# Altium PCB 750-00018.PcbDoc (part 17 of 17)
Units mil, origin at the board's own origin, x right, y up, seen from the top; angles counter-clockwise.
Board outline 7086.64 x 6299.21 mil, 8 copper layers (Top Layer, L2, L3, L4, L5, L6, L7, Bottom Layer), stack 60.6 mil thick; 1356 components, 1054 nets, 4851 pads, 4296 vias.
Unrouted connection lines stored in the file: 12.
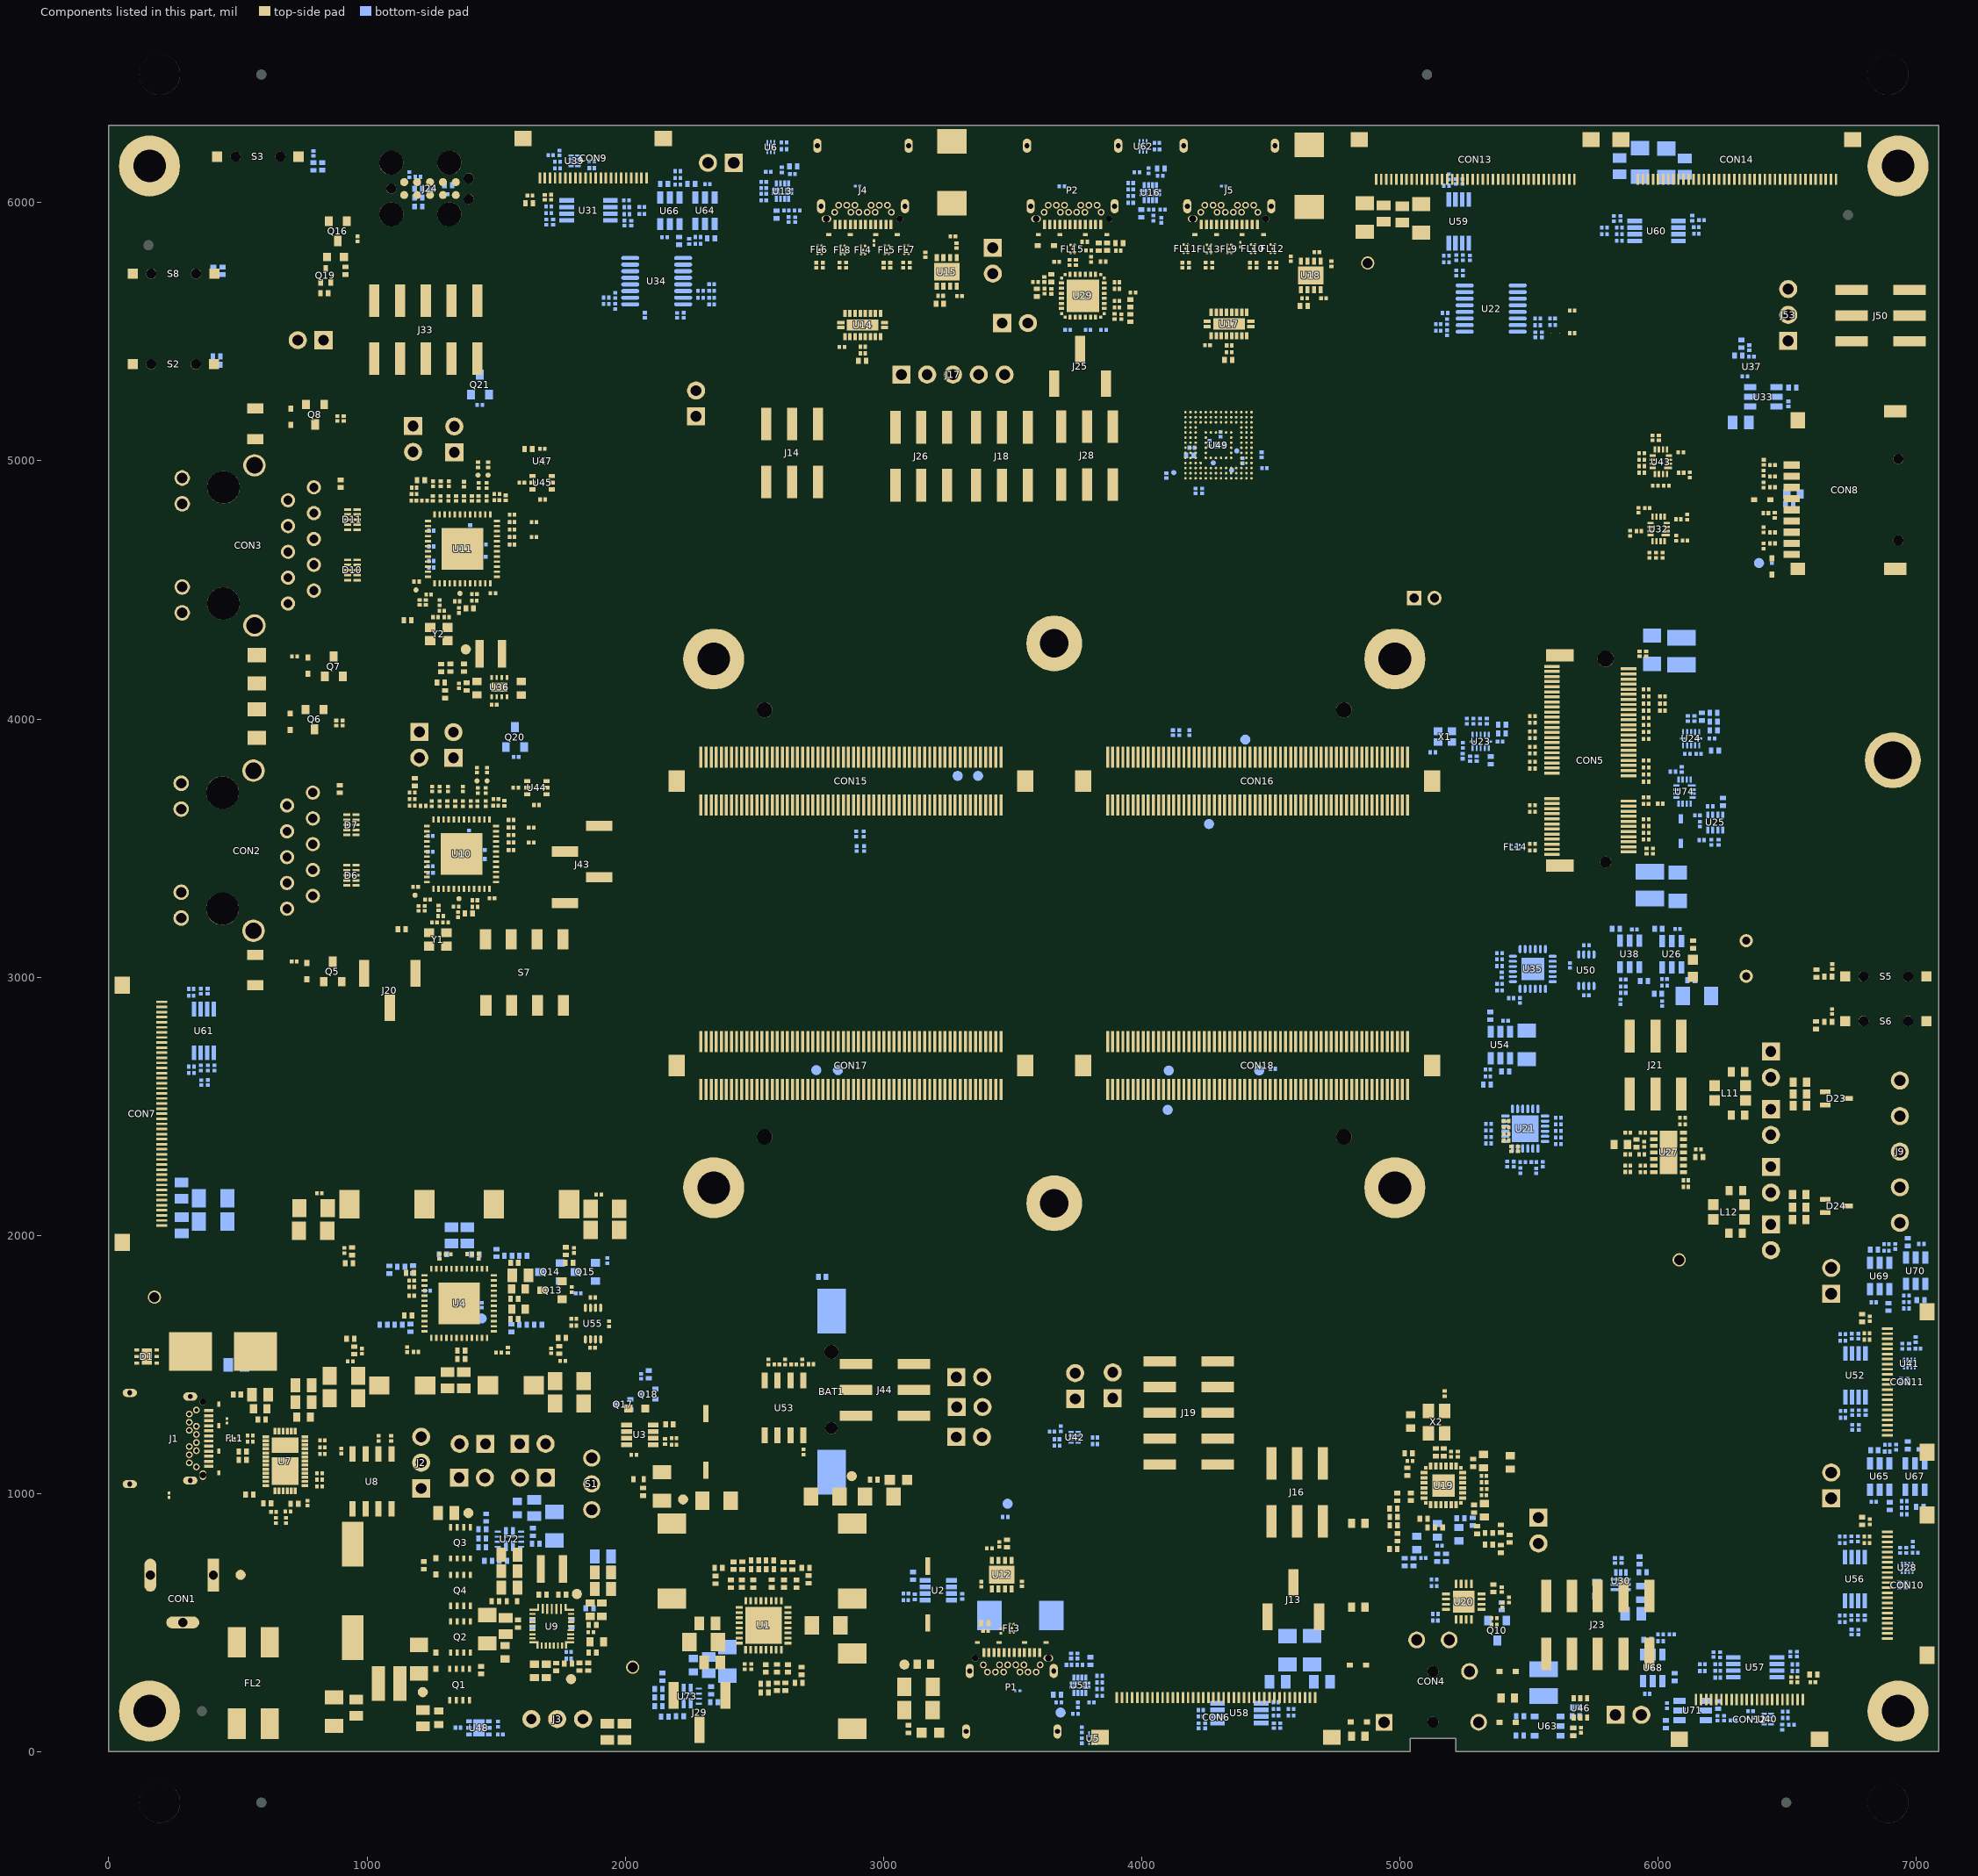
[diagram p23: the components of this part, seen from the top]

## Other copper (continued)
Bottom Layer:
  rectangle net NetU7_15: 630.69,1157.17 735.02,1217.4
  pour cut-out: 6735.52,5981.81 ccw(c6735.52,5952.12) 6705.84,5952.12 ccw(c6735.52,5952.12) 6735.52,5922.44 ccw(c6735.52,5952.12) 6765.21,5952.12 ccw(c6735.52,5952.12)
  pour cut-out: 153.48,5865.01 ccw(c153.48,5835.32) 123.79,5835.32 ccw(c153.48,5835.32) 153.48,5805.64 ccw(c153.48,5835.32) 183.16,5835.32 ccw(c153.48,5835.32)
  pour cut-out: 360.48,187.17 ccw(c360.48,157.48) 330.79,157.48 ccw(c360.48,157.48) 360.48,127.8 ccw(c360.48,157.48) 390.16,157.48 ccw(c360.48,157.48)
  region net CSI_HV: 1556.98,776.15 1572.73,776.15 1572.73,870.64 1586.68,884.6 1673.62,884.6 1690.32,901.29 1761.18,901.29 1761.18,956.41 1766.59,961.81 1766.59,976.53 1760.66,982.46 1695.93,982.46 1690.32,976.85 1690.32,956.41 1665.52,931.61 1564.12,931.61 1556.98,924.47
  pour cut-out: 7020.34,1093.61 7020.34,1089.61 7006.35,1089.61 7006.35,1093.61
  region net VDD_3V3: 6161.12,185.89 6482.03,185.89 6495.05,172.88 6495.05,122.93 6514.39,122.93 6519.03,118.29 6519.03,96.64 6532.87,96.64 6550.98,114.75 6550.98,283.07 6571.45,303.54 6571.45,365.04 6561.4,375.09 6494.09,375.09 6483.1,386.08 6260.9,386.08 6247.89,373.07 6247.59,373.37 6156.38,373.37 6140.75,357.74 6140.75,287.32 6158.45,269.61 6218.44,269.61 6228.24,279.42 6228.24,295.24 6178.4,295.24 6168.73,304.91 6168.73,346.6 6178.5,356.37 6504.75,356.37 6504.75,356.3 6522.83,356.3 6532.94,346.2 6532.94,301.81 6524.95,293.82 6524.95,230.82 6512.01,217.87 6169.47,217.87 6161.12,209.52
  region net VDD_3V3: 6923.73,1612.26 6938.16,1597.84 6938.16,1573.72 6979.75,1573.72 6979.75,1594.12 6984.55,1598.92 7005.3,1598.92 7005.3,1632.47 7046.4,1673.57 7046.4,1835.11 7022.78,1835.11 7022.78,1691.94 6962.36,1631.52 6777.84,1631.52 6758.59,1650.77 6723.15,1650.77 6718.03,1645.65 6718.03,1584.08 6732.47,1584.08 6732.47,1603.89 6740.85,1612.27 6767.43,1612.27
  region net VDD_3V3: 6716.5,800.01 6730.36,800.01 6730.36,818.09 6740.46,828.2 6784.64,828.2 6799.75,813.09 6920,813.09 6928.6,804.48 6928.6,783.06 6969.16,783.06 6969.32,783.22 6969.32,803.42 6972.86,806.96 6994.57,806.96 7043.96,856.34 7043.96,1038.49 7020.34,1038.49 7020.34,868.47 6995.31,843.44 6803.16,843.44 6779.9,866.71 6721.62,866.71 6716.5,861.59
  pour cut-out: 2160.66,5944.53 2160.66,5940.53 2146.67,5940.53 2146.67,5944.53
  pour cut-out: 2320.52,5992.41 2320.52,5996.41 2334.5,5996.41 2334.5,5992.41
  pour cut-out: 6110,172.11 6106,172.11 6106,186.1 6110,186.1
  pour cut-out: 5967.91,301.59 5967.91,297.59 5953.92,297.59 5953.92,301.59
  pour cut-out: 6845.44,1042.32 6845.44,1038.32 6831.46,1038.32 6831.46,1042.32
  pour cut-out: 6845.44,1818.75 6845.44,1814.75 6831.46,1814.75 6831.46,1818.75
  pour cut-out: 7008.79,1886.51 7008.79,1890.51 7022.77,1890.51 7022.77,1886.51
  region net VDD_3V3_B: 7022.41,1890.23 7022.41,1990.03 7022.41,2002.81 7026.38,2006.78 7046.4,2006.78 7046.4,1890.23
  region net VDD_3V3_C: 7020.34,1093.61 7043.96,1093.61 7043.96,1140.85 7048.51,1145.4 7048.51,1218.43 7040.98,1225.96 7025.52,1225.96 7020.34,1220.77
  region net VDD_3V3_D: 6106,209.52 6015.65,209.52 6001.01,194.88 6001.01,184.15 6008.25,176.91 6016.98,176.91 6021.17,181.1 6053.96,181.1 6058.75,185.89 6106,185.89
  region net VDD_3V3: 2123.26,5995.65 2123.26,6043.48 2102.79,6063.95 2102.79,6083.99 2111.59,6092.8 2135.91,6092.8 2144.37,6084.34 2144.37,6053.3 2146.88,6050.79 2146.88,5995.65
  region net VDD_3V3_A: 2146.88,5940.53 2146.88,5876.27 2149.62,5873.52 2149.62,5857.7 2142.36,5850.43 2112.85,5850.43 2105.21,5858.07 2105.21,5875.24 2123.26,5893.29 2123.26,5940.53
  region net DP_HV: 2344.88,267.76 2420.98,191.66 2439.91,191.66 2450.46,202.21 2450.46,302.78 2430.33,322.9 2246.03,322.9 2246.03,285.38 2246.03,168.19 2261.78,168.19 2261.78,252.01 2277.53,267.76
  region net LS_12V: 1460.55,144.97 1460.55,110.1 1536.1,110.1 1544.75,118.74 1544.75,147.94 1532.72,159.96 1475.55,159.96
  region net VPD_output: 1424.84,912.66 1487.4,912.66 1529.42,870.64 1529.42,829.3 1545.17,829.3 1545.17,953.05 1527.43,970.79 1351.17,970.79 1315.84,935.46 1315.84,815.65 1336.22,795.26 1387.55,795.26 1407.61,815.32 1407.61,895.43
  region net V_SYS: 1299.98,1986.92 1299.98,1905.57 1315.1,1890.46 1397.86,1890.46 1414.13,1906.73 1414.13,1986.92
  region net DP_HV: 4694.89,366.07 4694.89,310.96 4684.04,300.1 4684.04,244.6 4633.34,244.6 4624.03,253.91 4624.03,366.07
  region net DP_HV: 241.46,2088.86 256.88,2088.86 375.99,2088.86 375.99,2018 320.87,2018 320.87,2037.97 307.33,2051.5 236.57,2051.5 233.66,2054.42 233.66,2081.06
  region net PER_12V: 1405.43,110.1 1365.12,110.1 1339.25,135.98 1339.25,145.5 1345.17,151.42 1398.86,151.42 1405.43,144.86
  region net VDD_CSI_5V: 6638.09,1132.68 6716.88,1132.68 6756.12,1093.44 6831.66,1093.44 6831.66,1179.03 6796.33,1214.36 6518.49,1214.36 6010.87,706.74 5946.12,706.74 5946.12,683.06 5963.9,683.06 5985.95,661.01 5985.95,616.11 5978.04,608.2 5921.13,608.2 5894.8,634.54 5865.27,634.54 5865.27,593.92 5887.37,571.82 5905.77,571.82 5916.3,561.29 5916.3,508.14 5873.06,464.9 5873.06,367.99 5888.34,352.71 5954.13,352.71 5954.13,448.71
  region net VDD_CSI_5V: 2334.3,5941.3 2334.3,5877.79 2337.86,5874.23 2337.86,5850.54 2370.66,5850.54 2388.88,5868.76 2388.88,5910.34 2357.92,5941.3
  region net VDD_CSI_5V_A: 2334.3,5996.41 2334.3,6050.66 2321.13,6063.83 2321.13,6087.2 2285.33,6123 2285.33,6154.06 2355.33,6154.06 2355.33,6113.36 2381.28,6087.41 2381.28,6019.78 2357.92,5996.41
  region net VDD_CSI_5V: 6831.66,1869.87 6831.66,1955.46 6824.42,1962.7 6786.34,1962.7 6777.6,1953.96 6777.6,1900.3 6808.04,1869.87
  region net VDD_CSI_5V_B: 6831.66,1814.75 6779.31,1814.75 6685.08,1908.98 6670.39,1908.98 6670.39,1838.98 6689.76,1838.98 6795.78,1732.96 6831.66,1732.96
  region net VDD_CSI_5V_C: 6831.66,1038.32 6782.26,1038.32 6704.02,1116.56 6670.39,1116.56 6670.39,1046.56 6698.49,1046.56 6785.62,959.42 6831.66,959.42
  region net VDD_CSI_5V_D: 5930.5,297.59 5900.02,267.1 5900.02,143.18 5954.13,143.18 5954.13,195.3 5954.13,297.59
  region net NetL14_1: 5865.27,654.22 5977.81,654.22 5977.81,619.96 5972.84,614.99 5928.47,614.99 5901.04,642.41 5865.27,642.41
  region net VDD_5V: 5501.06,245.9 5501.06,185.44 5568.41,185.44 5606.3,147.56 5606.3,127.05 5607.44,125.91 5675.7,125.91 5675.7,205.46 5635.25,245.9
  region net VDD_3V3: 6003.62,6039.32 5996.27,6046.67 5996.27,6126.46 6129.85,6126.46 6129.85,6081.8 6087.37,6039.32
  region net VDD_3V3: 6078.61,3061.76 6078.61,3014.52 6067.85,3003.76 6067.85,2892.07 6122.97,2892.07 6122.97,3041.03 6102.23,3061.76
  region net VDD_3V3: 5414.29,2627.17 5417.69,2623.78 5520.26,2623.78 5555.61,2659.13 5555.61,2700.19 5545.52,2710.28 5414.52,2710.28 5414.29,2710.06
  region net VDD_3V3: 1801.82,5941.26 1801.82,5922.46 1744.82,5922.46 1739.87,5927.41 1664.45,5927.41 1654.23,5937.62 1654.23,5975.9 1670.59,5992.25 1700.59,5992.25 1700.59,5951.14 1700.38,5950.93 1710.05,5941.26 1712.64,5941.26
  region net VDD_3V3: 4528.7,365.4 4528.7,310.29 4539.55,299.43 4539.55,243.93 4592.09,243.93 4599.56,251.4 4599.56,365.4
  region net VDD_3V3: 308.26,2160.81 321.13,2173.68 321.13,2179.11 376.25,2179.11 376.25,2108.25 236.97,2108.25 232.09,2113.13 232.09,2158.48 234.42,2160.81
  region net NetC262_1: 6339.21,5381.49 6339.21,5370.24 6349.44,5370.24 6355.74,5376.54 6355.75,5393.09 6358.26,5395.61 6358.26,5411.44 6360.99,5414.16 6360.99,5434.91 6345.18,5434.91 6334.2,5445.89 6334.2,5447.53 6316.68,5447.53 6316.68,5396.17 6324.52,5396.17
  region net NetC262_1: 6339.21,5370.24 6339.21,5378.9
  region net NetC256_2: 6994.63,802.23 6978.81,802.23 6978.81,749.8 6967.65,738.64 6967.65,731.18 6989.3,731.18 6989.3,736.51 6992.38,739.59 6992.38,779.02 6994.63,781.28
  region net NetC260_2: 3716.66,1220.58 3722.25,1220.58 3722.25,1242.09 3716.38,1247.96 3655.44,1247.96 3655.44,1232.14 3705.11,1232.14
  region net NetC257_2: 1714.23,6191.7 1714.23,6175.88 1764.86,6175.88 1776.02,6164.72 1785.37,6164.72 1785.37,6186.37 1779.95,6186.37 1776.87,6189.45 1737.43,6189.45 1735.18,6191.7
  region net NetC259_2: 7003.2,1592.99 6987.38,1592.99 6987.38,1540.87 6976.22,1529.71 6976.22,1522.11 6997.87,1522.11 6997.87,1527.28 7000.95,1530.36 7000.95,1569.79 7003.2,1572.05
  region net NetC258_2: 6513.18,96.64 6513.18,112.47 6462.55,112.47 6451.4,123.63 6442.81,123.63 6442.81,101.97 6447.47,101.97 6450.55,98.9 6489.98,98.9 6492.24,96.64
  region net VDD_SD_3V3: 6332.51,5221.61 6333.11,5221.01 6333.11,5115.92 6338.48,5110.56 6390.95,5110.56 6398.35,5117.96 6398.35,5179.39 6379.75,5197.98 6379.75,5221.61
  region net NetC297_1: 6502.14,4819.35 6502.14,4843.06 6512.55,4853.48 6512.55,4889.03 6512.38,4889.2 6484.38,4889.2 6454.96,4859.79 6454.96,4828.04 6463.65,4819.35
  region net CSI_HV: 5827.11,673.91 5799.68,701.33 5742.36,701.33 5737.74,696.71 5737.74,648.58 5744.49,641.83 5780.49,641.83 5800.76,662.1 5846.24,662.1 5846.24,673.91
  region net VDD_3V3_M2: 6078.02,3194.25 6078.02,3116.88 6359.54,3116.88 6454.7,3212.04 6454.7,4074.77 6288.91,4240.57 6144.98,4240.57 6144.98,4240.38 5911.11,4240.38 5911.11,4239.99 5902.27,4231.16 5902.27,4181.2 5945.49,4137.99 6247.57,4137.99 6359.54,4026.01 6359.54,3539.86 6305.96,3486.27 5937.7,3486.27 5912.19,3460.76 5912.19,3378.43 6213.71,3378.43 6230.22,3361.91 6230.22,3225.15 6205.11,3200.03 6083.81,3200.03
  region net NetC233_1: 6157.32,4003.01 6155.37,4001.06 6155.37,3938.05 6163.24,3938.05 6169.6,3944.4 6208.88,3944.4 6208.88,4035.49 6208.64,4035.72 6190.86,4035.72 6190.86,4012.04 6181.84,4003.01
  region net USB_A_VBUS: 3362.9,488.34 3362.9,462.49 3394.05,431.34 3426.92,431.34 3457.39,461.81 3457.39,488.34
  region net U28_SW2: 1766.15,528.26 1734.1,528.26 1729.07,523.23 1729.07,492 1735.73,485.34 1767.89,485.34 1772.12,489.57 1772.12,522.3
  region net U28_SW1: 1665.75,529.02 1659.03,522.3 1659.03,491.55 1664.82,485.76 1694.91,485.76 1701.79,492.65 1701.71,492.73 1701.71,522.87 1695.57,529.02
  region net NetC76_2: 506.78,1426.66 516.08,1417.36 581.83,1417.36 588.74,1424.27 588.74,1509.37 574.02,1524.1 506.78,1524.1
  region net VDD_2V5: 2189.09,5606.29 2189.09,5570.47 2193.12,5566.44 2234.61,5566.44 2259.09,5590.92 2259.09,5606.29
  region net VDD_2V5: 5456.05,5495.86 5482.06,5469.84 5494.92,5469.84 5516.23,5491.15 5558.01,5491.15 5558.01,5505 5555.22,5507.78 5456.05,5507.78
  region net VDD_2V5: 841.07,2173.2 837.28,2169.41 837.28,2148.99 840.32,2145.95 880.54,2145.95 883.54,2148.96 883.54,2169.01 879.36,2173.2
  region net VDD_1V8: 5593.81,5559.43 5594.03,5559.2 5594.03,5517.54 5627.53,5517.54 5631.01,5521.02 5631.01,5555.73 5627.31,5559.43
  region net VDD_1V8: 5390.9,3920.92 5390.9,3902.75 5387.32,3899.17 5340.49,3899.17 5340.49,3845.9 5362.78,3845.9 5404.74,3887.87 5404.74,3920.92
  region net VDD_5V: 4037.87,5936.77 4037.87,5852.45 4068.76,5821.56 4090.86,5821.56 4097.84,5828.54 4097.84,5898.21 4087.77,5908.28 4087.77,5926.06 4064.08,5926.06 4053.69,5936.45 4053.69,5936.77
  region net VDD_5V: 5915.41,3062.2 5915.41,2980.19 5921.6,2974 5939.38,2974 5939.38,3061.86 5939.04,3062.2
  region net VDD_5V: 4052.74,6067.99 4052.74,6140.88 4050.57,6143.05 4068.34,6143.05 4068.34,6083.48 4063.2,6078.34 4063.2,6067.99
  region net VDD_5V: 2627.17,6066.14 2627.17,6152.27 2643.62,6152.27 2643.62,6090.48 2638.48,6085.33 2638.48,6066.14
  region net VDD_5V: 2625.09,5931.22 2625.09,5836.11 2633.45,5827.74 2660.58,5827.74 2668.93,5836.09 2668.93,5925.38 2663.09,5931.22
  region net VDD_5V: 3678.59,208.89 3682.09,205.4 3682.09,183.22 3709.42,183.22 3740.75,214.54 3740.75,226.1 3740.75,237.88 3683.89,237.88 3678.59,232.58
  pour cut-out: 1737.28,4558.7 1737.28,4550.11 1741.22,4550.11 1741.22,4558.7
  pour cut-out: 5583.56,3547.03 5583.56,4597.25 5583.56,4736.88 5729.14,4882.46 5729.14,4969.9 5827.13,5067.89 6067.74,5065.61 6144.74,4988.61 6144.74,4540.78 6011.58,4407.62 5964.27,4407.62 5878.71,4322.06 5878.71,4096.25 5813.49,4031.04 5814.14,4030.39 5814.14,3631.99 5739.84,3557.7 5699.07,3557.7 5671.74,3585.02 5658.99,3585.02 5621.34,3547.37 5584.29,3547.37
  pour cut-out: 4029.85,3890.17 4006.77,3867.09 3926.5,3867.09 3883.85,3909.73 3883.85,4085.84 3946.07,4148.05 4024.33,4148.05 4112.13,4060.25 4112.13,4016.1
  pour cut-out: 6351.17,4943.27 6346.44,4938.54 6333.79,4951.18 6338.46,4955.85 6350.94,4943.37
  pour cut-out: 4714.42,4468.12 4719.15,4472.85 4731.8,4460.2 4727.13,4455.53 4714.65,4468.01
  pour cut-out: 1597.4,3642.16 1604.09,3642.16 1604.09,3624.28 1597.49,3624.28 1597.49,3641.92
  pour cut-out: 1596.65,3355.1 1603.34,3355.1 1603.34,3337.22 1596.74,3337.22 1596.74,3354.86
  pour cut-out: 1612.88,3389.54 1619.57,3389.54 1619.57,3371.66 1612.97,3371.66 1612.97,3389.31
  pour cut-out: 1625.89,3499.46 1632.58,3499.46 1632.58,3481.58 1625.98,3481.58 1625.98,3499.23
  pour cut-out: 1629.74,3567.37 1636.43,3567.37 1636.43,3549.48 1629.83,3549.48 1629.83,3567.13
  text ".layer_Name" at 11119.18,-642.91 h100

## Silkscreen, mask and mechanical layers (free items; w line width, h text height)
Top Overlay:
  drawing of 230 lines, arcs and shapes, not listed
  text "Debug UART reset" at 3385.36,6054.63 h35
  text "Wake-up" at 399.02,6000.84 h65
  text "CSI_A" at 1868.69,5895.85 h100
  text "LVDS_D" at 5170.98,5867.49 h100
  text "LVDS_E" at 6088.95,5867.49 h100
  text "Debug UART" at 4100.61,5827.14 h80 r90
  text "RTS" at 6701.78,5825.85 h30
  text "RX" at 6859.87,5825.42 h30
  text "CTS" at 6701.78,5776.1 h30
  text "TX" at 6859.87,5775.66 h30
  text "MCU_UART_B" at 6182.63,5738.38 h35
  text "GND" at 6700.99,5724.88 h30
  text "OSM_1V8" at 6859.87,5721.11 h30
  text "RESET" at 1728.68,5708.49 h35 r90
  text "nTRST" at 1816.69,5707.29 h35 r90
  text "TDI" at 1907.55,5707.29 h35 r90
  text "NC" at 1987.19,5707.29 h35 r90
  text "TDO" at 2074.88,5703.34 h35 r90
  text "GND" at 2427.38,5618.62 h30 r90
  text "CTS_GPIO_B_3" at 2503.94,5618.62 h25 r90
  text "RTS_GPIO_B_2" at 2580.5,5618.62 h25 r90
  text "USB_C" at 2757.51,5606.08 h100
  text "GPIO_A_4" at 3555.87,5603.25 h35 r90
  text "USB_D" at 4223.03,5597.32 h100
  text "GND" at 4809.57,5596.41 h100
  text "2-3 : J50 CON" at 6157.61,5594.76 h25
  text "TMS" at 1817.11,5582.63 h35 r90
  text "GND" at 1907.97,5582.63 h35 r90
  text "CLK" at 1987.61,5582.63 h35 r90
  text "GND" at 2075.29,5581.57 h35 r90
  text "RESET" at 66.1,5548.92 h65
  text "JTAG" at 1634.2,5537.17 h100 r90
  text "GPIO_D_6" at 4215.85,5529.63 h20 r90
  text "CAM_C_MCK" at 4028.99,5528.19 h20 r90
  text "PWM_4" at 4060.51,5529.03 h20 r90
  text "CAM_D_MCK" at 4101.45,5526.77 h20 r90
  text "PWM_5" at 4138.52,5526.77 h20 r90
  text "GND" at 685.91,5515.41 h25
  text "1-2 : M2" at 6243.47,5496.17 h25
  text "VDD_1V8" at 1736.5,5466.3 h35 r90
  text "UART_D" at 2346.38,5454.45 h100 r90
  text "1.8V" at 2425.07,5439.69 h30 r90
  text "TX" at 2497.63,5439.69 h30 r90
  text "RX" at 2570.19,5439.69 h30 r90
  text "GND" at 3881.6,5415.51 h30 r90
  text "SCL" at 3677.87,5411.1 h30 r90
  text "GPIO_VS_0" at 3084.89,5395.48 h25 r90
  text "GPIO_VS_1" at 3130.56,5395.48 h25 r90
  text "GPIO_V0_0" at 3176.23,5395.48 h25 r90
  text "GPIO_V0_1" at 3221.9,5395.48 h25 r90
  text "GPIO_V0_2" at 3267.57,5395.48 h25 r90
  text "CAM_A_MCK" at 4039.29,5324.73 h20 r90
  text "GND" at 4103.15,5324.73 h20 r90
  text "CAM_B_MCK" at 4182.34,5324.73 h20 r90
  text "PWM_3" at 4219.41,5324.73 h20 r90
  text "GPIO_A_0 / SDIO_B_RST" at 639.56,5266.41 h30
  text "GND" at 2108.18,5251.16 h35
  text "SDA" at 3783.76,5245.46 h35 r90
  text "Micro SD" at 6603.24,5236.38 h100
  text "RX" at 2566.95,5225.87 h30 r90
  text "TX" at 2666.95,5225.87 h30 r90
  text "1.8V" at 2766.95,5225.87 h30 r90
  text "GPIO_C_1" at 1018.46,5202.56 h30
  text "PWR_BTN" at 68.4,5199.23 h65
  text "GPIO_C_0" at 1297.06,5194.31 h35
  text "I2C_B_MCU" at 3620.61,5194.39 h50 r90
  text "GND" at 3114.82,5150.66 h30 r90
  text "RTS" at 3214.81,5150.66 h30 r90
  text "CTS" at 3313.56,5150.66 h30 r90
  text "JTAG_RTCK" at 1928.55,5134.22 h35
  text "1.8V" at 3113.33,4840.87 h30 r90
  text "TX" at 3212.92,4840.87 h30 r90
  text "RX" at 3316.11,4840.87 h30 r90
  text "UART_A" at 2955.75,4781.4 h100 r90
  text "UART_C" at 2445.26,4769.14 h100 r90
  text "RTS" at 2560.98,4743.15 h30 r90
  text "CTS" at 2665.67,4743.15 h30 r90
  text "GND" at 2765.67,4743.15 h30 r90
  text "GPIO_B_0" at 2511.09,4705.06 h30 r90
  text "OSM Carrier" at 3158.13,4657.04 h250
  text "Ethernet 1" at 9.23,4161.88 h100
  text "GPIO_A_2" at 941.2,3945.22 h30
  text "GPIO_A_1" at 1401.99,3925.39 h35
  text "Ethernet 0" at 9.69,3876.57 h100
  text "GND" at 1740.53,3875.43 h25
  text "FORCE_RECOVERY#" at 1740.53,3804.53 h25
  text "BOOT_SEL1#" at 1740.53,3729.45 h25
  text "BOOT_SEL0#" at 1740.53,3654.38 h25
  text "Key-E" at 5610.61,3266.41 h100
  text "Vol Up" at 6745.25,3134.53 h100
  text "L" at 1848.24,3082.57 h60
  text "H" at 1848.24,2840.12 h60
  text "Vol Down" at 6165.97,2785.28 h100
  text "CAN BUS" at 6739.04,2684.28 h80
  text "GPIO_VM_2" at 5582.91,2659.25 h35 r90
  text "GPIO_VM_1" at 5662.33,2659.25 h35 r90
  text "GPIO_VM_0" at 5741.75,2659.25 h35 r90
  text "CAN1_H" at 6571.94,2616.63 h35
  text "GPIO_C_2" at 1026.87,2565.17 h35 r90
  text "GPIO_C_3" at 1125.87,2563.51 h35 r90
  text "BOOT_SEL1#" at 1594.1,2471.66 h40 r90
  text "BOOT_SEL0#" at 1489.77,2462.38 h40 r90
  text "CAN1_L" at 6571.94,2400.35 h35
  text "GPIO_VM_5" at 5582.91,2349.95 h35 r90
  text "GPIO_VM_4" at 5664.43,2349.95 h35 r90
  text "GPIO_VM_3" at 5745.96,2349.95 h35 r90
  text "RGB_BL_PWM / LVDS_E_BL_PWM / PWM_2" at 1349.59,2322.66 h35 r90
  text "GND" at 6687.62,2311.02 h35
  text "FORCE_RECOVERY#" at 1699.84,2281.47 h40 r90
  text "RGB Display" at 370.36,2267.23 h100 r90
  text "CAN2_H" at 6571.94,2201.49 h35
  text "GND" at 5880.46,1990.53 h100
  text "CAN2_L" at 6571.94,1975.91 h35
  text "EEPORM I2C" at 282.78,1909.71 h60
  text "POP" at 298.42,1862.92 h25
  text "NOPOP" at 398.63,1862.92 h25
  text "Function" at 572.47,1862.92 h25
  text "J37" at 420.38,1813.11 h25
  text "J40" at 300.66,1810.95 h25
  text "Connecting to" at 532.53,1803.36 h25
  text "J42" at 420.38,1771.66 h25
  text "J41" at 300.66,1769.51 h25
  text "PD and BQ" at 558.52,1766.89 h25
  text "J37" at 300.66,1722.79 h25
  text "J40" at 418.64,1720.63 h25
  text "GND" at 3048.09,1718.32 h30
  text "Connecting to" at 533.79,1713.65 h25
  text "V_BAT" at 3339.95,1712.92 h30
  text "/ WP_(IO2)" at 2797.44,1707.83 h25
  text "SDO_(IO0)" at 2548.15,1703.9 h30
  text "GND" at 99.18,1692.61 h60 r90
  text "J42" at 300.66,1681.34 h25
  text "J41" at 418.64,1679.18 h25
  text "CPU" at 611.34,1678.86 h25
  text "SCK" at 2547.59,1640.34 h30
  text "SDI_(IO1)" at 2804.07,1640.34 h30
  text "VCC_OUT_IO" at 3339.95,1622.84 h30
  text "SPI_A" at 2501.16,1606.55 h30 r90
  text "SPI_A_CS1# / GPIO_A_6" at 3048.62,1597.26 h30
  text "/ HOLD_(IO3)" at 2544.32,1572.68 h25
  text "CS0#" at 2860.02,1571.58 h30
  text "/ GPIO_A_5" at 3964.79,1543.51 h35 r90
  text "I2S_AB_RST" at 3889.84,1540.5 h35 r90
  text "GPIO_A_3" at 3045.71,1534.1 h30
  text "CAM_B (3.3V)" at 3623.48,1533.65 h30
  text "SCL" at 3588.97,1441.46 h30
  text "750-00018-5-0" at 5418.41,1351.54 h70 r90
  text "Common OSM-M/ OSM-S Carrier Board" at 5597.29,1345 h45 r90
  text "SDA" at 3588.97,1341.6 h30
  text "GND" at 3847.28,1265.14 h30
  text "SCL" at 1275.15,1260.94 h35
  text "OFF" at 1893.93,1251.76 h30
  text "PD_M_I2C" at 885.73,1249.06 h30
  text "GPIO_C_5 / DSI_A_BL_EN / LVDS_A_BL_EN" at 4524.7,1194.55 h30 r90
  text "GPIO_C_4 / DSI_A_VDD_EN / LVDS_A_VDD_EN" at 4657.17,1193.38 h30 r90
  text "DSI_A_TE" at 4735.13,1193.74 h30 r90
  text "PWM_0 / DSI_A_E_BL_PWM / LVDS_A_BL_PWM" at 4999.08,1175.09 h25 r90
  text "CSI_B" at 6780.64,1162.49 h100 r90
  text "GPIO_D_2 / CAM_C_PWR" at 6126.75,1097.61 h35 r90
  text "GPIO_D_3 / CAM_C_RST#" at 6230.52,1097.61 h35 r90
  text "GND" at 6322.63,1097.61 h35 r90
  text "GPIO_D_4 / CAM_D_PWR" at 6426.41,1097.61 h35 r90
  text "GPIO_D_5 / CAM_D_RST#" at 6530.18,1097.61 h35 r90
  text "GND" at 1302.46,1086.72 h25 r90
  text "SDO" at 3971.21,1004.94 h35
  text "CS0#" at 3796.65,993.62 h35
  text "SDA" at 1269.28,959.18 h35
  text "SDI" at 3971.21,939.82 h35
  text "GPIO_B_5 / I2C_C_SDA / I2C_DISPLAY_DAT" at 4879.8,938.41 h25 r90
  text "GPIO_B_4 / I2C_C_SCL / I2C_DISPLAY_CLK" at 4809.96,934.78 h25 r90
  text "ON" at 1986.44,927.39 h30
  text "CS1#/GPIO_A_7" at 3541.7,928.06 h35
  text "SPI_C" at 4099.38,884.22 h50
  text "SPKOUT_N" at 5611.56,878.66 h40
  text "SCK" at 3971.21,874.71 h35
  text "SCK" at 3829.47,872.18 h35
  text "DC 12V/3A" at 36.75,869.21 h80
  text "EEPORM I2C" at 1502.63,838.57 h60
  text "SPI_B" at 3532.83,818.62 h50
  text "SDI" at 3856.47,810.35 h35
  text "CS1#/GPIO_D_7" at 3971.21,797.94 h35
  text "SPKOUT_P" at 5612.29,766.15 h40
  text "V_SYS" at 1817.55,764.98 h35
  text "SDO" at 3829.8,738.83 h35
  text "CS0#" at 3971.21,721.16 h35
  text "USB_A" at 3598.25,500.29 h100
  text "GPIO_B_7 / LVDS_D_BL_EN" at 4283.92,450.71 h25 r90
  text "GPIO_C_6 / CAM_A_PWR" at 6126.75,420.44 h35 r90
  text "GPIO_C_7 / CAM_A_RST#" at 6230.52,420.44 h35 r90
  text "GND" at 6322.63,420.44 h35 r90
  text "GPIO_D_0 / CAM_B_PWR" at 6426.41,420.44 h35 r90
  text "GPIO_D_1 / CAM_B_RST#" at 6530.18,420.44 h35 r90
  text "CSI_C" at 6800.96,419.03 h100 r90
  text "BAT_SENSE-" at 1943.7,403.29 h30
  text "GPIO_B_6 / LVDS_D_VDD_EN" at 4413.95,393.5 h25 r90
  text "LVDS_D_BL_PWM / PWM_1" at 4157.14,391.55 h25 r90
  text "CSI_D" at 6083.21,282.91 h100
  text "AUDIO JACK" at 4962.49,277 h75 r90
  text "MIPI_DSI_LVDS_A" at 3903.08,265.57 h100
  text "GND" at 2524.05,30.62 h35 r90
  text "ADC_1" at 2599.15,30.62 h35 r90
  text "ADC_0" at 2672.95,30.62 h35 r90
  text "GND" at 1442.92,24.8 h35 r90
  text "TS" at 1506.29,24.8 h35 r90
  text "BAT_SENSE" at 1573.94,24.8 h35 r90
  text ".layer_Name" at 11129.82,-628.81 h100
Bottom Overlay:
  text ".layer_Name" at 11119.18,-642.91 h100
Top Paste:
  text ".layer_Name" at 11119.18,-642.91 h100
Bottom Paste:
  text ".layer_Name" at 11119.18,-642.91 h100
Top Solder:
  text ".layer_Name" at 11119.18,-642.91 h100
Bottom Solder:
  text ".layer_Name" at 11119.18,-642.91 h100
Board Outline:
  the board outline again, w5
Title Block:
  drawing of 40 lines, arcs and shapes, not listed
  text "DATE" at 14726.77,9980.02 h70
  text "ENG." at 15301.77,9971.02 h70
  text "REV." at 10952.77,9970.02 h70
  text "DESCRIPTION" at 12343.77,9970.02 h70
  text "Initial release" at 11276.74,9807.24 h70
  text "2024/5/28" at 14600.62,9807.11 h70
  text "1-0" at 10957.83,9802.98 h70
  text "Replace the OSM module with an interposer board" at 11276.12,9643.08 h70
  text "2024/11/5" at 14600.62,9642.25 h70
  text "2-0" at 10957.64,9637.27 h70
  text "Modify the design" at 11275.18,9478.22 h70
  text "2025/3/31" at 14599.73,9474.92 h70
  text "3-0" at 10956.7,9472.41 h70
  text "Fix issues with previous versions" at 11275.22,9313.67 h70
  text "2025/9/19" at 14599.77,9310.37 h70
  text "4-0" at 10956.75,9307.86 h70
  text "1. OSM pin name changed" at 11275.74,9141.81 h70
  text "2025/11/6" at 14600.29,9138.51 h70
  text "5-0" at 10957.27,9136 h70
  text "2. Delete J15" at 11277.47,9010.43 h70
  text "APPROVALS" at 11219.18,707.09 h70
  text "DATE" at 12319.18,707.09 h70
  text ".ProjectAddress1" at 14292.18,520.22 h60
  text "DRAWN:" at 10919.18,507.09 h50
  text ".ProjectDrawnBy" at 11419.18,507.09 h50
  text ".ProjectDrawnDate" at 12219.18,507.09 h50
  text ".ProjectAddress2" at 14292.18,420.22 h60
  text "Phone: .ProjectPhone" at 14292.18,320.22 h60
  text "CHECKED:" at 10919.18,307.09 h50
  text ".ProjectCheckedBy" at 11419.18,307.09 h50
  text ".ProjectCheckedDate" at 12219.18,307.09 h50
  text "www.ezurio.com" at 14292.18,220.22 h60
  text "APPROVED:" at 10919.18,107.09 h50
  text ".ProjectApprovedBy" at 11419.18,107.09 h50
  text ".ProjectApprovedDate" at 12219.18,107.09 h50
  text "Title:" at 10901.35,-95.71 h50
  text "PCB, .ProjectTitle" at 11039.14,-284.69 h150
  text "REV:" at 15255.17,-467.41 h50
  text "Layer:" at 10921.03,-485.47 h50
  text "Project:" at 12969.18,-492.91 h50
  text "DWG NO." at 14069.18,-492.91 h50
  text ".ProjectPCBRevision" at 15267.77,-599.26 h70
  text "'.ProjectPCBNumber'" at 14339.17,-629.36 h70
  text ".ProjectNumber" at 13219.18,-642.91 h60
  text "Customer: .ProjectCustomerName" at 12219.18,-792.91 h50
  text "Last Modified:" at 13019.18,-792.91 h50
  text "SIZE:" at 14069.18,-792.91 h50
  text "SCALE:" at 14449.18,-792.91 h50
  text "SHEET:" at 14919.18,-792.91 h50
  text "File:" at 10903.17,-797.36 h50
  text ".PCB_File_Name_No_Path" at 10987.96,-879.17 h50
  text "'.Print_Date'" at 13019.18,-892.91 h50
  text ".Print_Time" at 13469.18,-892.91 h50
  text "1:1" at 14519.18,-912.91 h50
  text "1 OF 1" at 15059.18,-912.91 h50
  text "B" at 14109.18,-952.91 h120
Mechanical 3:
  lines w1: 6908.87,3771.52 6908.87,3249.18 5885.24,3249.18 5885.24,3429.29 ccw(c5865.56,3429.29) 5865.56,3448.98 5727.76,3448.98 5727.76,3712.76 5841.94,3712.76 ccw(c5841.94,3736.38) 5865.56,3736.38 ccw(c5841.94,3736.38) 5841.94,3760 5727.76,3760 5727.76,4230.48 5865.56,4230.48 ccw(c5865.56,4250.16) 5885.24,4250.16 5885.24,4430.28 6908.87,4430.28 6908.87,3908.56
  lines w10: 2086.62,3208.66 5236.22,3208.66 ; 3661.42,1771.65 3661.42,4645.67 ; 2086.62,1811.02 2086.62,4606.3 2125.99,4645.67 5196.85,4645.67 5236.22,4606.3 5236.22,1811.02 5196.85,1771.65 2125.99,1771.65 2086.62,1811.02
Mechanical 7:
  lines w4: 2086.62,1811.02 2125.99,1771.65 5196.85,1771.65 5236.22,1811.02 5236.22,4606.3 5196.85,4645.67 2125.99,4645.67 2086.62,4606.3 2086.62,1811.02
  lines w6: 4783.93,4428.82 4923.27,4428.82 4923.27,4429.07 4880.17,4474.87 4877.23,4385.72 4923.03,4428.82 ; 2900.52,4276.27 4783.93,4276.27 4783.93,4581.38 2900.52,4581.38 2900.52,4276.27 ; 5007.88,4421.26 5181.1,4421.26 5181.1,4515.74 5007.88,4515.74 5007.88,4421.26
  lines w10: 5133.86,4507.87 5133.86,4468.5 5173.36,4468.5
  text "Kingmate, Q110-S-02-2-38/20/30-E1 / Pin Header, 1x2, 2.0mm pitch" at 2976.86,4330.94 h55
Board:
  lines w5: 4822.75,0 7086.63,0 7086.63,6299.21 0,6299.21 0,0 5039.28,0 5039.28,51.18 5216.45,51.18 5216.45,0
Top Assembly:
  text ".layer_Name" at 11136.67,-642.91 h100
Bottom Assembly:
  text ".layer_Name" at 11136.67,-642.91 h100
Drill Drawing:
  drawing of 288 lines, arcs and shapes, not listed
  text "Layer" at 11775.48,8666.21 h60
  text "Name" at 12185.39,8666.21 h60
  text "Material" at 13115.13,8666.21 h60
  text "Thickness" at 13704.99,8666.21 h60
  text "Constant" at 14354.82,8666.21 h60
  text "PCB NOTES:" at 5800.49,8580.63 h156.25
  text "Top Overlay" at 12185.39,8546.21 h60
  text "Top Solder" at 12185.39,8426.21 h60
  text "SM-003" at 13115.13,8426.21 h60
  text "0.80mil" at 13704.99,8426.21 h60
  text "3.5" at 14354.82,8426.21 h60
  text "1. Thickness: 1.6mm Tolerance+/-0.1mm" at 5778.3,8400.94 h60
  text "1" at 11775.48,8306.21 h60
  text "Top Layer" at 12185.39,8306.21 h60
  text "1.40mil" at 13704.99,8306.21 h60
  text "Dielectric 1" at 12185.39,8186.21 h60
  text "PP-013" at 13115.13,8186.21 h60
  text "3.50mil" at 13704.99,8186.21 h60
  text "3.78" at 14354.82,8186.21 h60
  text "2" at 11775.48,8066.21 h60
  text "L2" at 12185.39,8066.21 h60
  text "CF-004" at 13115.13,8066.21 h60
  text "1.40mil" at 13704.99,8066.21 h60
  text "Dielectric 3" at 12185.39,7946.21 h60
  text "PP-016" at 13115.13,7946.21 h60
  text "4.20mil" at 13704.99,7946.21 h60
  text "3.87" at 14354.82,7946.21 h60
  text "3" at 11775.48,7826.21 h60
  text "L3" at 12185.39,7826.21 h60
  text "1.40mil" at 13704.99,7826.21 h60
  text "Dielectric 2" at 12185.39,7706.21 h60
  text "PP-008" at 13115.13,7706.21 h60
  text "7.00mil" at 13704.99,7706.21 h60
  text "3.73" at 14354.82,7706.21 h60
  text "2. Impedance: / 1) Impedance=50 ohm +/-10%, Traces: TOP and BOT Layer to L2 and L7 Layer, Trace Width: 6 mil. / 2) Impedance=50 ohm +/-10%, Traces: L3 Layer to L2/L4 ayer, Trace Width: 5 mil. / 3) Differential=85 ohm+/-10%, Traces: TOP and BOT Layer to L2 and L7 Layer, Trace Width: 6 mil, Spacing: 5mil. / 4) Differential=90 ohm+/-10%, Traces: TOP and BOT Layer to: L2 and L7, Layer, Trace Width: 5 mil, Spacing: 5mil. / 5) Differential=100 ohm+/-10%, Traces: TOP and BOT Layer to: L2 and L7 Layer, Trace Width: 4 mil, Spacing: 5.5mil." at 5766.51,7637.62 h60
  text "4" at 11775.48,7586.21 h60
  text "L4" at 12185.39,7586.21 h60
  text "1.40mil" at 13704.99,7586.21 h60
  text "Dielectric3" at 12185.39,7466.21 h60
  text "Core-015" at 13115.13,7466.21 h60
  text "20.00mil" at 13704.99,7466.21 h60
  text "4" at 14354.82,7466.21 h60
  text "5" at 11775.48,7346.21 h60
  text "L5" at 12185.39,7346.21 h60
  text "1.40mil" at 13704.99,7346.21 h60
  text "Dielectric5" at 12185.39,7226.21 h60
  text "PP-008" at 13115.13,7226.21 h60
  text "7.00mil" at 13704.99,7226.21 h60
  text "3.73" at 14354.82,7226.21 h60
  text "6" at 11775.48,7106.21 h60
  text "L6" at 12185.39,7106.21 h60
  text "1.40mil" at 13704.99,7106.21 h60
  text "Dielectric 4" at 12185.39,6986.21 h60
  text "PP-016" at 13115.13,6986.21 h60
  text "4.20mil" at 13704.99,6986.21 h60
  text "3.87" at 14354.82,6986.21 h60
  text "7" at 11775.48,6866.21 h60
  text "L7" at 12185.39,6866.21 h60
  text "CF-004" at 13115.13,6866.21 h60
  text "1.40mil" at 13704.99,6866.21 h60
  text "Dielectric4" at 12185.39,6746.21 h60
  text "PP-013" at 13115.13,6746.21 h60
  text "3.50mil" at 13704.99,6746.21 h60
  text "3.78" at 14354.82,6746.21 h60
  text "8" at 11775.48,6626.21 h60
  text "Bottom Layer" at 12185.39,6626.21 h60
  text "1.40mil" at 13704.99,6626.21 h60
  text "Bottom Solder" at 12185.39,6506.21 h60
  text "SM-003" at 13115.13,6506.21 h60
  text "0.80mil" at 13704.99,6506.21 h60
  text "3.5" at 14354.82,6506.21 h60
  text "Bottom Overlay" at 12185.39,6386.21 h60
  text "Symbol" at 8370.89,6165.32 h72
  text "Count" at 8876.77,6165.32 h72
  text "Hole Size" at 9536.59,6165.32 h72
  text "Plated" at 10686.25,6165.32 h72
  text "Hole Type" at 11192.13,6165.32 h72
  text "Drill Layer Pair" at 11925.93,6165.32 h72
  text "Via/Pad" at 13425.48,6165.32 h72
  text "Pad Shape" at 14015.33,6165.32 h72
  text "24" at 8876.77,6015.32 h60
  text "7.87mil (0.200mm)" at 9536.59,6015.32 h60
  text "PTH" at 10686.25,6015.32 h60
  text "Round" at 11192.13,6015.32 h60
  text "Top Layer - Bottom Layer" at 11925.93,6015.32 h60
  text "Via" at 13425.48,6015.32 h60
  text "Rounded" at 14015.33,6015.32 h60
  text "H" at 8341.8,6005.33 h66.67
  text "3994" at 8876.77,5865.32 h60
  text "8.00mil (0.203mm)" at 9536.59,5865.32 h60
  text "PTH" at 10686.25,5865.32 h60
  text "Round" at 11192.13,5865.32 h60
  text "Top Layer - Bottom Layer" at 11925.93,5865.32 h60
  text "Via" at 13425.48,5865.32 h60
  text "Rounded" at 14015.33,5865.32 h60
  text "M" at 8341.8,5855.33 h66.67
  text "266" at 8876.77,5715.32 h60
  text "10.00mil (0.254mm)" at 9536.59,5715.32 h60
  text "PTH" at 10686.25,5715.32 h60
  text "Round" at 11192.13,5715.32 h60
  text "Top Layer - Bottom Layer" at 11925.93,5715.32 h60
  text "Via" at 13425.48,5715.32 h60
  text "Rounded" at 14015.33,5715.32 h60
  text "12" at 8876.77,5565.32 h60
  text "12.00mil (0.305mm)" at 9536.59,5565.32 h60
  text "PTH" at 10686.25,5565.32 h60
  text "Round" at 11192.13,5565.32 h60
  text "Top Layer - Bottom Layer" at 11925.93,5565.32 h60
  text "Via" at 13425.48,5565.32 h60
  text "Rounded" at 14015.33,5565.32 h60
  text "I" at 8352.91,5555.33 h66.67
  text "60" at 8876.77,5415.32 h60
  text "15.75mil (0.400mm)" at 9536.59,5415.32 h60
  text "PTH" at 10686.25,5415.32 h60
  text "Round" at 11192.13,5415.32 h60
  text "Top Layer - Bottom Layer" at 11925.93,5415.32 h60
  text "Pad" at 13425.48,5415.32 h60
  text "Rounded" at 14015.33,5415.32 h60
  text "20" at 8876.77,5265.32 h60
  text "19.69mil (0.500mm)" at 9536.59,5265.32 h60
  text "PTH" at 10686.25,5265.32 h60
  text "Slot" at 11192.13,5265.32 h60
  text "Top Layer - Bottom Layer" at 11925.93,5265.32 h60
  text "Pad" at 13425.48,5265.32 h60
  text "Rounded" at 14015.33,5265.32 h60
  text "5" at 8876.77,5115.32 h60
  text "25.59mil (0.650mm)" at 9536.59,5115.32 h60
  text "NPTH" at 10686.25,5115.32 h60
  text "Round" at 11192.13,5115.32 h60
  text "Top Layer - Bottom Layer" at 11925.93,5115.32 h60
  text "Pad" at 13425.48,5115.32 h60
  text "Rounded" at 14015.33,5115.32 h60
  text "5" at 8876.77,4965.32 h60
  text "25.59mil (0.650mm)" at 9536.59,4965.32 h60
  text "NPTH" at 10686.25,4965.32 h60
  text "Slot" at 11192.13,4965.32 h60
  text "Top Layer - Bottom Layer" at 11925.93,4965.32 h60
  text "Pad" at 13425.48,4965.32 h60
  text "Rounded" at 14015.33,4965.32 h60
  text "2" at 8876.77,4815.32 h60
  text "31.50mil (0.800mm)" at 9536.59,4815.32 h60
  text "PTH" at 10686.25,4815.32 h60
  text "Round" at 11192.13,4815.32 h60
  text "Top Layer - Bottom Layer" at 11925.93,4815.32 h60
  text "Pad" at 13425.48,4815.32 h60
  text "Rounded" at 14015.33,4815.32 h60
  text "2" at 8876.77,4665.32 h60
  text "35.00mil (0.889mm)" at 9536.59,4665.32 h60
  text "PTH" at 10686.25,4665.32 h60
  text "Round" at 11192.13,4665.32 h60
  text "Top Layer - Bottom Layer" at 11925.93,4665.32 h60
  text "Pad" at 13425.48,4665.32 h60
  text "(Mixed)" at 14015.33,4665.32 h60
  text "Q" at 8341.8,4655.33 h66.67
  text "20" at 8876.77,4515.32 h60
  text "35.04mil (0.890mm)" at 9536.59,4515.32 h60
  text "PTH" at 10686.25,4515.32 h60
  text "Round" at 11192.13,4515.32 h60
  text "Top Layer - Bottom Layer" at 11925.93,4515.32 h60
  text "Pad" at 13425.48,4515.32 h60
  text "Rounded" at 14015.33,4515.32 h60
  text "R" at 8341.8,4505.33 h66.67
  text "3" at 8876.77,4365.32 h60
  text "35.43mil (0.900mm)" at 9536.59,4365.32 h60
  text "PTH" at 10686.25,4365.32 h60
  text "Slot" at 11192.13,4365.32 h60
  text "Top Layer - Bottom Layer" at 11925.93,4365.32 h60
  text "Pad" at 13425.48,4365.32 h60
  text "(Mixed)" at 14015.33,4365.32 h60
  text "E" at 8341.8,4355.33 h66.67
  text "3" at 8876.77,4215.32 h60
  text "39.00mil (0.991mm)" at 9536.59,4215.32 h60
  text "NPTH" at 10686.25,4215.32 h60
  text "Round" at 11192.13,4215.32 h60
  text "Top Layer - Bottom Layer" at 11925.93,4215.32 h60
  text "Pad" at 13425.48,4215.32 h60
  text "Rounded" at 14015.33,4215.32 h60
  text "12" at 8876.77,4065.32 h60
  text "39.37mil (1.000mm)" at 9536.59,4065.32 h60
  text "NPTH" at 10686.25,4065.32 h60
  text "Round" at 11192.13,4065.32 h60
  text "Top Layer - Bottom Layer" at 11925.93,4065.32 h60
  text "Pad" at 13425.48,4065.32 h60
  text "Rounded" at 14015.33,4065.32 h60
  text "4" at 8876.77,3915.32 h60
  text "39.37mil (1.000mm)" at 9536.59,3915.32 h60
  text "PTH" at 10686.25,3915.32 h60
  text "Round" at 11192.13,3915.32 h60
  text "Top Layer - Bottom Layer" at 11925.93,3915.32 h60
  text "Pad" at 13425.48,3915.32 h60
  text "Rounded" at 14015.33,3915.32 h60
  text "11" at 8876.77,3765.32 h60
  text "40.16mil (1.020mm)" at 9536.59,3765.32 h60
  text "PTH" at 10686.25,3765.32 h60
  text "Round" at 11192.13,3765.32 h60
  text "Top Layer - Bottom Layer" at 11925.93,3765.32 h60
  text "Pad" at 13425.48,3765.32 h60
  text "Rounded" at 14015.33,3765.32 h60
  text "55" at 8876.77,3615.32 h60
  text "42.00mil (1.067mm)" at 9536.59,3615.32 h60
  text "PTH" at 10686.25,3615.32 h60
  text "Round" at 11192.13,3615.32 h60
  text "Top Layer - Bottom Layer" at 11925.93,3615.32 h60
  text "Pad" at 13425.48,3615.32 h60
  text "(Mixed)" at 14015.33,3615.32 h60
  text "3" at 8876.77,3465.32 h60
  text "42.91mil (1.090mm)" at 9536.59,3465.32 h60
  text "PTH" at 10686.25,3465.32 h60
  text "Round" at 11192.13,3465.32 h60
  text "Top Layer - Bottom Layer" at 11925.93,3465.32 h60
  text "Pad" at 13425.48,3465.32 h60
  text "Rounded" at 14015.33,3465.32 h60
  text "F" at 8341.8,3455.33 h66.67
  text "3" at 8876.77,3315.32 h60
  text "43.31mil (1.100mm)" at 9536.59,3315.32 h60
  text "NPTH" at 10686.25,3315.32 h60
  text "Round" at 11192.13,3315.32 h60
  text "Top Layer - Bottom Layer" at 11925.93,3315.32 h60
  text "Pad" at 13425.48,3315.32 h60
  text "Rounded" at 14015.33,3315.32 h60
  text "10" at 8876.77,3165.32 h60
  text "43.31mil (1.100mm)" at 9536.59,3165.32 h60
  text "PTH" at 10686.25,3165.32 h60
  text "Round" at 11192.13,3165.32 h60
  text "Top Layer - Bottom Layer" at 11925.93,3165.32 h60
  text "Pad" at 13425.48,3165.32 h60
  text "(Mixed)" at 14015.33,3165.32 h60
  text "G" at 8341.8,3155.33 h66.67
  text "8" at 8876.77,3015.32 h60
  text "44.88mil (1.140mm)" at 9536.59,3015.32 h60
  text "PTH" at 10686.25,3015.32 h60
  text "Round" at 11192.13,3015.32 h60
  text "Top Layer - Bottom Layer" at 11925.93,3015.32 h60
  text "Pad" at 13425.48,3015.32 h60
  text "Rounded" at 14015.33,3015.32 h60
  text "A" at 8341.8,3005.33 h66.67
  text "1" at 8876.77,2865.32 h60
  text "47.24mil (1.200mm)" at 9536.59,2865.32 h60
  text "NPTH" at 10686.25,2865.32 h60
  text "Round" at 11192.13,2865.32 h60
  text "Top Layer - Bottom Layer" at 11925.93,2865.32 h60
  text "Pad" at 13425.48,2865.32 h60
  text "Rounded" at 14015.33,2865.32 h60
  text "J" at 8341.8,2855.33 h66.67
  text "1" at 8876.77,2715.32 h60
  text "55.12mil (1.400mm)" at 9536.59,2715.32 h60
  text "NPTH" at 10686.25,2715.32 h60
  text "Round" at 11192.13,2715.32 h60
  text "Top Layer - Bottom Layer" at 11925.93,2715.32 h60
  text "Pad" at 13425.48,2715.32 h60
  text "Rounded" at 14015.33,2715.32 h60
  text "N" at 8341.8,2705.33 h66.67
  text "4" at 8876.77,2565.32 h60
  text "60.00mil (1.524mm)" at 9536.59,2565.32 h60
  text "NPTH" at 10686.25,2565.32 h60
  text "Round" at 11192.13,2565.32 h60
  text "Top Layer - Bottom Layer" at 11925.93,2565.32 h60
  text "Pad" at 13425.48,2565.32 h60
  text "Rounded" at 14015.33,2565.32 h60
  text "K" at 8341.8,2555.33 h66.67
  text "1" at 8876.77,2415.32 h60
  text "62.99mil (1.600mm)" at 9536.59,2415.32 h60
  text "NPTH" at 10686.25,2415.32 h60
  text "Round" at 11192.13,2415.32 h60
  text "Top Layer - Bottom Layer" at 11925.93,2415.32 h60
  text "Pad" at 13425.48,2415.32 h60
  text "Rounded" at 14015.33,2415.32 h60
  text "4" at 8876.77,2265.32 h60
  text "64.17mil (1.630mm)" at 9536.59,2265.32 h60
  text "PTH" at 10686.25,2265.32 h60
  text "Round" at 11192.13,2265.32 h60
  text "Top Layer - Bottom Layer" at 11925.93,2265.32 h60
  text "Pad" at 13425.48,2265.32 h60
  text "Rounded" at 14015.33,2265.32 h60
  text "S" at 8341.8,2255.33 h66.67
  text "4" at 8876.77,2115.32 h60
  text "93.50mil (2.375mm)" at 9536.59,2115.32 h60
  text "NPTH" at 10686.25,2115.32 h60
  text "Round" at 11192.13,2115.32 h60
  text "Top Layer - Bottom Layer" at 11925.93,2115.32 h60
  text "Pad" at 13425.48,2115.32 h60
  text "Rounded" at 14015.33,2115.32 h60
  text "2" at 8876.77,1965.32 h60
  text "110.24mil (2.800mm)" at 9536.59,1965.32 h60
  text "NPTH" at 10686.25,1965.32 h60
  text "Round" at 11192.13,1965.32 h60
  text "Top Layer - Bottom Layer" at 11925.93,1965.32 h60
  text "Pad" at 13425.48,1965.32 h60
  text "Rounded" at 14015.33,1965.32 h60
  text "B" at 8341.8,1955.33 h66.67
  text "12" at 8876.77,1815.32 h60
  text "125.98mil (3.200mm)" at 9536.59,1815.32 h60
  text "NPTH" at 10686.25,1815.32 h60
  text "Round" at 11192.13,1815.32 h60
  text "Top Layer - Bottom Layer" at 11925.93,1815.32 h60
  text "Pad" at 13425.48,1815.32 h60
  text "Rounded" at 14015.33,1815.32 h60
  text "T" at 8341.8,1805.33 h66.67
  text "1" at 8876.77,1665.32 h60
  text "145.67mil (3.700mm)" at 9536.59,1665.32 h60
  text "PTH" at 10686.25,1665.32 h60
  text "Round" at 11192.13,1665.32 h60
  text "Top Layer - Bottom Layer" at 11925.93,1665.32 h60
  text "Pad" at 13425.48,1665.32 h60
  text "Rounded" at 14015.33,1665.32 h60
  text "4" at 8876.77,1515.32 h60
  text "157.48mil (4.000mm)" at 9536.59,1515.32 h60
  text "NPTH" at 10686.25,1515.32 h60
  text "Round" at 11192.13,1515.32 h60
  text "Top Layer - Bottom Layer" at 11925.93,1515.32 h60
  text "Pad" at 13425.48,1515.32 h60
  text "Rounded" at 14015.33,1515.32 h60
  text "O" at 8341.8,1505.33 h66.67
  text "4556 Total" at 8876.77,1365.32 h60
  text "Slot definitions :" at 8370.89,1220.35 h60
  text "Routed Path Length" at 9403.58,1220.35 h60
  text "= Calculated from tool start centre position to tool end centre position." at 10506.25,1220.35 h60
  text "Hole Length" at 9403.58,1120.37 h60
  text "= Routed Path Length + Tool Size = Slot length as defined in the PCB layout" at 10096.38,1120.37 h60
Panel:
  lines w5: 0,6692.92 0,6299.22 ; 0,6692.91 7086.61,6692.91 7086.63,6299.22 ; 1558.11,0.97 ccw(c1558.11,-38.4) 1558.11,-77.77 1915.22,-77.77 ccw(c1915.22,-38.4) 1915.22,0.97 ; 2695.64,6299.21 cw(c2695.64,6338.58) 2695.64,6377.95 4566.45,6377.95 cw(c4566.45,6338.58) 4566.45,6299.21 ; 3287.02,0 ccw(c3287.02,-39.37) 3287.02,-78.74 3706.36,-78.74 ccw(c3706.36,-39.37) 3706.36,0 ; 4822.75,0 7086.64,0 ; 4943.04,0 ccw(c4943.04,-74.8) 4943.04,-149.61 5296.94,-149.61 ccw(c5296.94,-74.8) 5296.94,0 ; 5216.45,0 5216.45,51.18 5039.28,51.18 5039.28,0 0,0 ; 0,6299.21 7086.63,6299.21 ; 0,6299.22 0,0 ; 0,0 0,-393.7 393.7,-393.7 7086.64,-393.7 7086.64,0 ; 7086.64,0 7086.63,6299.21
  text "Routing" at 3413.5,6320.54 h40
  text "Routing" at 5072.83,-44.1 h20
  text "Routing" at 1662.22,-45.7 h20
  text "Routing" at 3431.81,-46.63 h20
  text ".layer_Name" at 11116.67,-642.15 h100

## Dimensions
5133.86,4468.5 to 5236.22,4606.3 on Mechanical 7
5133.86,4468.5 to 5196.85,4645.67 on Mechanical 7
5055.12,4468.5 to 5133.86,4468.5 on Mechanical 7
0,6692.92 to 7086.63,6692.92 on Mechanical 16
0,6299.22 to 0,6692.92 on Mechanical 16
7086.63,6299.21 to 7259.93,6297.85 on Mechanical 16
7086.64,0 to 7259.93,-1.36 on Mechanical 16
0,0 to 0,-393.7 on Mechanical 16
5039.28,51.18 to 5216.45,51.18 on Mechanical 16
0,0 to 5039.28,0 on Mechanical 16
5216.45,51.18 to 5216.45,0 on Mechanical 16
0,6299.21 to 0,0 on Mechanical 16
